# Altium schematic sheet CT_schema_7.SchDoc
size 367 x 243 mm
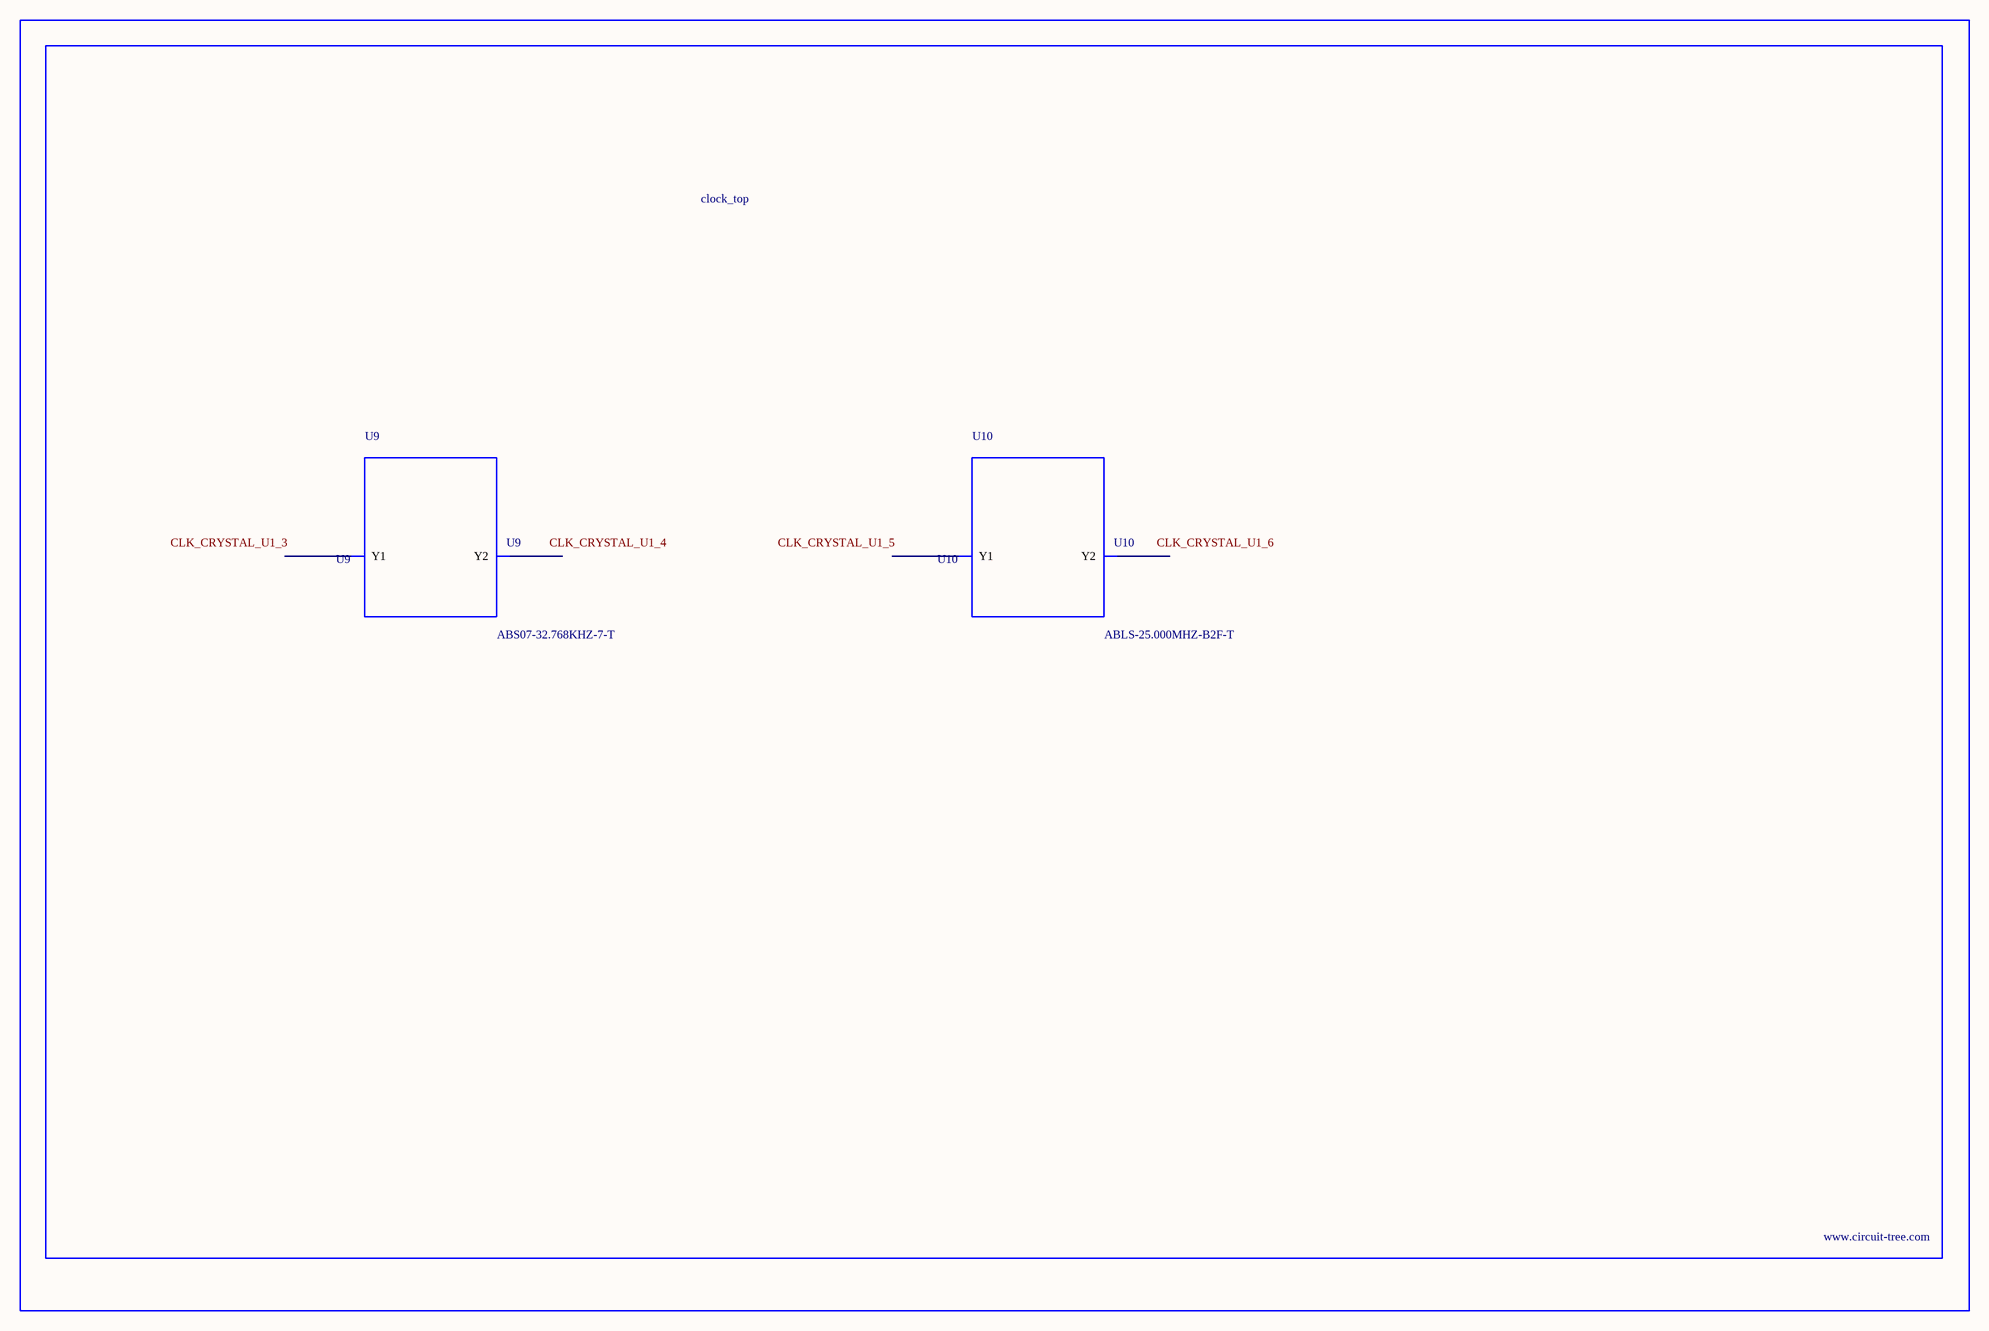
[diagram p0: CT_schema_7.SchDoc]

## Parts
BORDER6  (no value)
U9  ABS07-32.768KHZ-7-T  [ABS07-32.768KHZ-7-T]
U10  ABLS-25.000MHZ-B2F-T  [ABLS-25.000MHZ-B2F-T]

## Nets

Not connected (* = marked no-connect by the designer): U9 1(Y1) 2(Y2); U10 1(Y1) 2(Y2)

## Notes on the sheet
- Labels drawn without touching a wire or pin: CLK_CRYSTAL_U1_3, CLK_CRYSTAL_U1_4, CLK_CRYSTAL_U1_5, CLK_CRYSTAL_U1_6

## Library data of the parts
BORDER6 = BORDER_PAGE6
